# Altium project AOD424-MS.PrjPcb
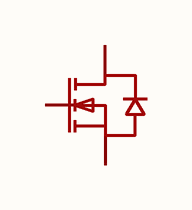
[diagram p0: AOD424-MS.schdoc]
1 sheet, 1 parts. Net scope: global (net labels, ports and power ports of the same name join across sheets).

## Sheet AOD424-MS.schdoc
size 127 x 101 mm

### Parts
Q?  aod424-ms  [TO-252-3_L6.6-W6.1-P4.58-LS10.0-BR]  (value not drawn)

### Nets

Not connected (* = marked no-connect by the designer): Q? 1(G) 2(S) 3(D)

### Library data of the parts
Q? = aod424-ms: 类型:1个N沟道;漏源电压(Vdss):20V;连续漏极电流(Id):60A;导通电阻(RDS(on)):6.5mΩ@4.5V,20A;耗散功率(Pd):60W;阈值电压(Vgs(th)):500mV;; Manufacturer: MSKSEMI(美森科); AddInBom: yes; ModelId: 72334c95445f48b7ab8d6cb8773a9d0c; ModelTransform: 259.842,394.17244,0,90,0,0,-36.024,0,0; Type: 1个N沟道; Drain to Source Voltage: 20V; Current - Continuous Drain(Id): 60A; Pd - Power Dissipation(Pd): 60W; Gate Threshold Voltage (Vgs(th)@Id): 500mV; Gate Charge(Qg): 27nC@10V; Input Capacitance(Ciss@Vds): 2nF@10V; Reverse Transfer Capacitance (Crss@Vds): 200pF@10V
